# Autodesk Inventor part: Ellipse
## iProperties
Shininess: 64.0
Length Units: 11272
Angle Units: 11279
Time Units: 11290
Mass Units: 11286
Length Display Precision: 3
Angle Display Precision: 2
Compacted: True
Part Number: Ellipse
Document SubType Name: Modeling
Created: 2004-07
Designer: Wolff
Material: Standard
Manufacturer: Standard
Standards Organization: Custom
Density: 0.0
Volumn: 0.0
Area: 0.0
PropertySet Name: Model Information
Control State: 0
Master: False
Checked Out: False
Author: Wolff
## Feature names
1. Extrusion1
